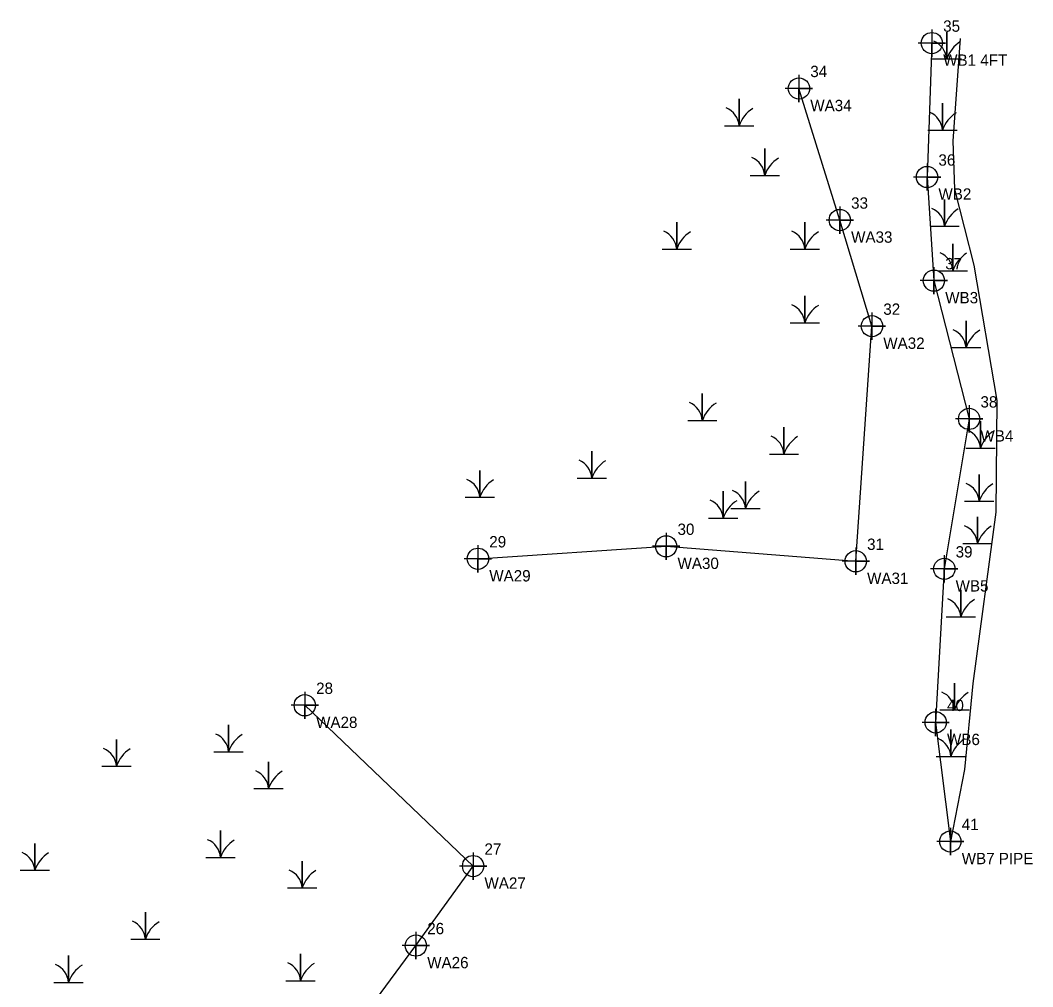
# Model space of a CAD drawing. Extents: x 2189822 to 2190837, y 387253 to 388663.
# Drawn here: x 2190230.2 to 2190453.2, y 388136.9 to 388349.8 of the extents above; entities that cross this region are included whole.
import ezdxf

# ---------------------------------------------------------------- set-up
doc = ezdxf.new("R2010")
doc.units = 0
for name, color, linetype in [('COGO Default Chain', 7, 'Continuous'), ('DTM Contours Major', 7, 'Continuous'), ('DTM Contours Minor', 7, 'Continuous'), ('Exist DTM Breakline Cogo Elevation', 7, 'Continuous'), ('Exist DTM Breakline Cogo Number', 7, 'Continuous')]:
    doc.layers.add(name, color=color, linetype=linetype)

msp = doc.modelspace()

# ---------------------------------------------------------------- linework, layer by layer
at = {"layer": 'DTM Contours Major'}
for points in [[(2190430.93, 388347.81), (2190430.93, 388341.81), (2190430.93, 388344.81), (2190433.93, 388344.81), (2190427.93, 388344.81)], [(2190401.66, 388337.81), (2190401.66, 388331.81), (2190401.66, 388334.81), (2190404.66, 388334.81), (2190398.66, 388334.81)], [(2190429.88, 388318.3), (2190429.88, 388312.3), (2190429.88, 388315.3), (2190432.88, 388315.3), (2190426.88, 388315.3)], [(2190410.65, 388308.82), (2190410.65, 388302.82), (2190410.65, 388305.82), (2190413.65, 388305.82), (2190407.65, 388305.82)], [(2190431.38, 388295.47), (2190431.38, 388289.47), (2190431.38, 388292.47), (2190434.38, 388292.47), (2190428.38, 388292.47)], [(2190417.74, 388285.44), (2190417.74, 388279.44), (2190417.74, 388282.44), (2190420.74, 388282.44), (2190414.74, 388282.44)], [(2190439.14, 388265.01), (2190439.14, 388259.01), (2190439.14, 388262.01), (2190442.14, 388262.01), (2190436.14, 388262.01)], [(2190372.42, 388236.94), (2190372.42, 388230.94), (2190372.42, 388233.94), (2190375.42, 388233.94), (2190369.42, 388233.94)], [(2190330.96, 388234.19), (2190330.96, 388228.19), (2190330.96, 388231.19), (2190333.96, 388231.19), (2190327.96, 388231.19)], [(2190414.17, 388233.64), (2190414.17, 388227.64), (2190414.17, 388230.64), (2190417.17, 388230.64), (2190411.17, 388230.64)], [(2190433.67, 388231.97), (2190433.67, 388225.97), (2190433.67, 388228.97), (2190436.67, 388228.97), (2190430.67, 388228.97)], [(2190292.82, 388201.91), (2190292.82, 388195.91), (2190292.82, 388198.91), (2190295.82, 388198.91), (2190289.82, 388198.91)], [(2190431.77, 388198.14), (2190431.77, 388192.14), (2190431.77, 388195.14), (2190434.77, 388195.14), (2190428.77, 388195.14)], [(2190435.01, 388171.9), (2190435.01, 388165.9), (2190435.01, 388168.9), (2190438.01, 388168.9), (2190432.01, 388168.9)], [(2190329.9, 388166.48), (2190329.9, 388160.48), (2190329.9, 388163.48), (2190332.9, 388163.48), (2190326.9, 388163.48)], [(2190317.29, 388148.97), (2190317.29, 388142.97), (2190317.29, 388145.97), (2190320.29, 388145.97), (2190314.29, 388145.97)]]:
    msp.add_lwpolyline(points, dxfattribs=at)
for centre in [(2190430.93, 388344.81), (2190401.66, 388334.81), (2190429.88, 388315.3), (2190410.65, 388305.82), (2190431.38, 388292.47), (2190417.74, 388282.44), (2190439.14, 388262.01), (2190372.42, 388233.94), (2190330.96, 388231.19), (2190414.17, 388230.64), (2190433.67, 388228.97), (2190292.82, 388198.91), (2190431.77, 388195.14), (2190435.01, 388168.9), (2190329.9, 388163.48), (2190317.29, 388145.97)]:
    msp.add_circle(centre, 2.34, dxfattribs=at)
at = {"layer": 'Exist DTM Breakline Cogo Elevation'}
for p, q in [((2190434.21, 388343.98), (2190434.21, 388343.98)), ((2190388.49, 388329.25), (2190388.49, 388329.25)), ((2190433.29, 388328.32), (2190433.29, 388328.32)), ((2190394.13, 388318.32), (2190394.13, 388318.32)), ((2190433.75, 388307.12), (2190433.75, 388307.12)), ((2190374.74, 388302.09), (2190374.74, 388302.09)), ((2190402.95, 388302.09), (2190402.95, 388302.09)), ((2190435.59, 388297.33), (2190435.59, 388297.33)), ((2190402.95, 388285.86), (2190402.95, 388285.86)), ((2190438.47, 388280.4), (2190438.47, 388280.4)), ((2190380.38, 388264.35), (2190380.38, 388264.35)), ((2190398.36, 388256.94), (2190398.36, 388256.94)), ((2190441.64, 388258.26), (2190441.64, 388258.26)), ((2190356.06, 388251.65), (2190356.06, 388251.65)), ((2190331.38, 388247.41), (2190331.38, 388247.41)), ((2190441.35, 388246.54), (2190441.35, 388246.54)), ((2190384.97, 388242.83), (2190384.97, 388242.83)), ((2190389.9, 388244.95), (2190389.9, 388244.95)), ((2190441, 388237.21), (2190441, 388237.21)), ((2190437.32, 388221.08), (2190437.32, 388221.08)), ((2190435.94, 388200.58), (2190435.94, 388200.58)), ((2190276.04, 388191.33), (2190276.04, 388191.33)), ((2190435.13, 388190.33), (2190435.13, 388190.33)), ((2190251.36, 388188.15), (2190251.36, 388188.15)), ((2190284.85, 388183.21), (2190284.85, 388183.21)), ((2190274.27, 388168.05), (2190274.27, 388168.05)), ((2190233.38, 388165.22), (2190233.38, 388165.22)), ((2190292.25, 388161.34), (2190292.25, 388161.34)), ((2190257.7, 388150.06), (2190257.7, 388150.06)), ((2190240.78, 388140.53), (2190240.78, 388140.53)), ((2190291.9, 388140.88), (2190291.9, 388140.88))]:
    msp.add_line(p, q, dxfattribs=at)
for points in [[(2190430.99, 388341.31), (2190434.21, 388341.31), (2190434.21, 388347.23), (2190434.21, 388341.31), (2190437.44, 388341.31)], [(2190385.27, 388326.58), (2190388.49, 388326.58), (2190388.49, 388332.5), (2190388.49, 388326.58), (2190391.72, 388326.58)], [(2190430.07, 388325.64), (2190433.29, 388325.64), (2190433.29, 388331.56), (2190433.29, 388325.64), (2190436.52, 388325.64)], [(2190390.91, 388315.64), (2190394.13, 388315.64), (2190394.13, 388321.56), (2190394.13, 388315.64), (2190397.36, 388315.64)], [(2190430.53, 388304.45), (2190433.75, 388304.45), (2190433.75, 388310.37), (2190433.75, 388304.45), (2190436.98, 388304.45)], [(2190371.52, 388299.42), (2190374.74, 388299.42), (2190374.74, 388305.33), (2190374.74, 388299.42), (2190377.97, 388299.42)], [(2190399.72, 388299.42), (2190402.95, 388299.42), (2190402.95, 388305.33), (2190402.95, 388299.42), (2190406.17, 388299.42)], [(2190432.37, 388294.66), (2190435.59, 388294.66), (2190435.59, 388300.58), (2190435.59, 388294.66), (2190438.82, 388294.66)], [(2190399.72, 388283.19), (2190402.95, 388283.19), (2190402.95, 388289.11), (2190402.95, 388283.19), (2190406.17, 388283.19)], [(2190435.25, 388277.73), (2190438.47, 388277.73), (2190438.47, 388283.64), (2190438.47, 388277.73), (2190441.7, 388277.73)], [(2190377.16, 388261.67), (2190380.38, 388261.67), (2190380.38, 388267.59), (2190380.38, 388261.67), (2190383.61, 388261.67)], [(2190438.42, 388255.59), (2190441.64, 388255.59), (2190441.64, 388261.5), (2190441.64, 388255.59), (2190444.87, 388255.59)], [(2190395.14, 388254.26), (2190398.36, 388254.26), (2190398.36, 388260.18), (2190398.36, 388254.26), (2190401.59, 388254.26)], [(2190352.83, 388248.97), (2190356.06, 388248.97), (2190356.06, 388254.89), (2190356.06, 388248.97), (2190359.29, 388248.97)], [(2190328.16, 388244.74), (2190331.38, 388244.74), (2190331.38, 388250.66), (2190331.38, 388244.74), (2190334.61, 388244.74)], [(2190438.12, 388243.86), (2190441.35, 388243.86), (2190441.35, 388249.78), (2190441.35, 388243.86), (2190444.58, 388243.86)], [(2190386.68, 388242.27), (2190389.9, 388242.27), (2190389.9, 388248.19), (2190389.9, 388242.27), (2190393.13, 388242.27)], [(2190381.74, 388240.15), (2190384.97, 388240.15), (2190384.97, 388246.07), (2190384.97, 388240.15), (2190388.19, 388240.15)], [(2190437.78, 388234.53), (2190441, 388234.53), (2190441, 388240.45), (2190441, 388234.53), (2190444.23, 388234.53)], [(2190434.1, 388218.41), (2190437.32, 388218.41), (2190437.32, 388224.32), (2190437.32, 388218.41), (2190440.55, 388218.41)], [(2190432.71, 388197.9), (2190435.94, 388197.9), (2190435.94, 388203.82), (2190435.94, 388197.9), (2190439.16, 388197.9)], [(2190272.81, 388188.65), (2190276.04, 388188.65), (2190276.04, 388194.57), (2190276.04, 388188.65), (2190279.26, 388188.65)], [(2190431.91, 388187.65), (2190435.13, 388187.65), (2190435.13, 388193.57), (2190435.13, 388187.65), (2190438.36, 388187.65)], [(2190248.13, 388185.48), (2190251.36, 388185.48), (2190251.36, 388191.4), (2190251.36, 388185.48), (2190254.59, 388185.48)], [(2190281.62, 388180.54), (2190284.85, 388180.54), (2190284.85, 388186.46), (2190284.85, 388180.54), (2190288.08, 388180.54)], [(2190271.05, 388165.37), (2190274.27, 388165.37), (2190274.27, 388171.29), (2190274.27, 388165.37), (2190277.5, 388165.37)], [(2190230.16, 388162.55), (2190233.38, 388162.55), (2190233.38, 388168.47), (2190233.38, 388162.55), (2190236.61, 388162.55)], [(2190289.03, 388158.67), (2190292.25, 388158.67), (2190292.25, 388164.59), (2190292.25, 388158.67), (2190295.48, 388158.67)], [(2190254.48, 388147.38), (2190257.71, 388147.38), (2190257.71, 388153.3), (2190257.71, 388147.38), (2190260.93, 388147.38)], [(2190237.56, 388137.86), (2190240.78, 388137.86), (2190240.78, 388143.77), (2190240.78, 388137.86), (2190244.01, 388137.86)], [(2190288.67, 388138.21), (2190291.9, 388138.21), (2190291.9, 388144.13), (2190291.9, 388138.21), (2190295.13, 388138.21)]]:
    msp.add_lwpolyline(points, dxfattribs=at)
for centre, radius, start, end in [((2190429.61, 388340.97), 4.61, 4.1403, 67.535), ((2190441.05, 388339.03), 7.21, 122.1274, 161.6222), ((2190383.89, 388326.25), 4.61, 4.1403, 67.535), ((2190395.33, 388324.31), 7.21, 122.1274, 161.6222), ((2190428.69, 388325.31), 4.61, 4.1403, 67.535), ((2190440.13, 388323.37), 7.21, 122.1274, 161.6222), ((2190389.53, 388315.31), 4.61, 4.1403, 67.535), ((2190400.97, 388313.37), 7.21, 122.1274, 161.6222), ((2190429.15, 388304.12), 4.61, 4.1403, 67.535), ((2190440.59, 388302.18), 7.21, 122.1274, 161.6222), ((2190370.14, 388299.08), 4.61, 4.1403, 67.535), ((2190381.58, 388297.14), 7.21, 122.1274, 161.6222), ((2190398.35, 388299.08), 4.61, 4.1403, 67.535), ((2190409.79, 388297.14), 7.21, 122.1274, 161.6222), ((2190430.99, 388294.33), 4.61, 4.1403, 67.535), ((2190442.43, 388292.39), 7.21, 122.1274, 161.6222), ((2190398.35, 388282.86), 4.61, 4.1403, 67.535), ((2190409.79, 388280.92), 7.21, 122.1274, 161.6222), ((2190433.87, 388277.39), 4.61, 4.1403, 67.535), ((2190445.31, 388275.45), 7.21, 122.1274, 161.6222), ((2190375.78, 388261.34), 4.61, 4.1403, 67.535), ((2190387.23, 388259.4), 7.21, 122.1274, 161.6222), ((2190437.04, 388255.25), 4.61, 4.1403, 67.535), ((2190448.48, 388253.31), 7.21, 122.1274, 161.6222), ((2190393.76, 388253.93), 4.61, 4.1403, 67.535), ((2190405.2, 388251.99), 7.21, 122.1274, 161.6222), ((2190351.46, 388248.64), 4.61, 4.1403, 67.535), ((2190362.9, 388246.7), 7.21, 122.1274, 161.6222), ((2190326.78, 388244.41), 4.61, 4.1403, 67.535), ((2190338.22, 388242.47), 7.21, 122.1274, 161.6222), ((2190436.75, 388243.53), 4.61, 4.1403, 67.535), ((2190448.19, 388241.59), 7.21, 122.1274, 161.6222), ((2190385.3, 388241.94), 4.61, 4.1403, 67.535), ((2190396.74, 388240), 7.21, 122.1274, 161.6222), ((2190380.37, 388239.82), 4.61, 4.1403, 67.535), ((2190391.81, 388237.88), 7.21, 122.1274, 161.6222), ((2190436.4, 388234.2), 4.61, 4.1403, 67.535), ((2190447.85, 388232.26), 7.21, 122.1274, 161.6222), ((2190432.72, 388218.07), 4.61, 4.1403, 67.535), ((2190444.16, 388216.13), 7.21, 122.1274, 161.6222), ((2190431.34, 388197.57), 4.61, 4.1403, 67.535), ((2190442.78, 388195.63), 7.21, 122.1274, 161.6222), ((2190271.44, 388188.32), 4.61, 4.1403, 67.535), ((2190282.88, 388186.38), 7.21, 122.1274, 161.6222), ((2190430.53, 388187.32), 4.61, 4.1403, 67.535), ((2190441.97, 388185.38), 7.21, 122.1274, 161.6222), ((2190246.76, 388185.14), 4.61, 4.1403, 67.535), ((2190258.2, 388183.21), 7.21, 122.1274, 161.6222), ((2190280.25, 388180.21), 4.61, 4.1403, 67.535), ((2190291.69, 388178.27), 7.21, 122.1274, 161.6222), ((2190269.67, 388165.04), 4.61, 4.1403, 67.535), ((2190281.12, 388163.1), 7.21, 122.1274, 161.6222), ((2190228.78, 388162.22), 4.61, 4.1403, 67.535), ((2190240.22, 388160.28), 7.21, 122.1274, 161.6222), ((2190287.65, 388158.34), 4.61, 4.1403, 67.535), ((2190299.09, 388156.4), 7.21, 122.1274, 161.6222), ((2190253.11, 388147.05), 4.61, 4.1403, 67.535), ((2190264.55, 388145.11), 7.21, 122.1274, 161.6222), ((2190236.18, 388137.52), 4.61, 4.1403, 67.535), ((2190247.63, 388135.58), 7.21, 122.1274, 161.6222), ((2190287.3, 388137.88), 4.61, 4.1403, 67.535), ((2190298.74, 388135.94), 7.21, 122.1274, 161.6222)]:
    msp.add_arc(centre, radius, start, end, dxfattribs=at)
at = {"layer": 'Exist DTM Breakline Cogo Number'}
for points in [[(2190437.15, 388345.85), (2190435.54, 388323.27), (2190435.94, 388312.59), (2190440.18, 388295.86), (2190445.21, 388266.03), (2190445.01, 388241.43), (2190439.97, 388203.74), (2190438.16, 388184.79), (2190435.01, 388168.9)], [(2190430.93, 388344.81), (2190429.88, 388315.3), (2190431.38, 388292.47), (2190439.14, 388262.01), (2190433.67, 388228.97), (2190431.77, 388195.14), (2190435.01, 388168.9)], [(2190330.96, 388231.19), (2190372.42, 388233.94), (2190414.17, 388230.64), (2190417.74, 388282.44), (2190410.65, 388305.82), (2190401.66, 388334.81)], [(2190303.02, 388126.66), (2190317.29, 388145.97), (2190329.9, 388163.48), (2190292.82, 388198.91)]]:
    msp.add_lwpolyline(points, dxfattribs=at)

# ---------------------------------------------------------------- texts
at = {"layer": 'COGO Default Chain'}
for s, p in [('WB1 4FT', (2190433.43, 388339.81)), ('WA34', (2190404.16, 388329.81)), ('WB2', (2190432.38, 388310.3)), ('WA33', (2190413.15, 388300.82)), ('WB3', (2190433.88, 388287.47)), ('WA32', (2190420.24, 388277.44)), ('WB4', (2190441.64, 388257.01)), ('WA30', (2190374.92, 388228.94)), ('WA29', (2190333.46, 388226.19)), ('WA31', (2190416.67, 388225.64)), ('WB5', (2190436.17, 388223.97)), ('WA28', (2190295.32, 388193.91)), ('WB6', (2190434.27, 388190.14)), ('WB7 PIPE', (2190437.51, 388163.9)), ('WA27', (2190332.4, 388158.48)), ('WA26', (2190319.79, 388140.97))]:
    msp.add_text(s, height=2.5, dxfattribs=at).set_placement(p)
at = {"layer": 'DTM Contours Minor'}
for s, p in [('35', (2190433.43, 388347.31)), ('34', (2190404.16, 388337.31)), ('36', (2190432.38, 388317.8)), ('33', (2190413.15, 388308.32)), ('37', (2190433.88, 388294.97)), ('32', (2190420.24, 388284.94)), ('38', (2190441.64, 388264.51)), ('30', (2190374.92, 388236.44)), ('29', (2190333.46, 388233.69)), ('31', (2190416.67, 388233.14)), ('39', (2190436.17, 388231.47)), ('28', (2190295.32, 388201.41)), ('40', (2190434.27, 388197.64)), ('41', (2190437.51, 388171.4)), ('27', (2190332.4, 388165.98)), ('26', (2190319.79, 388148.47))]:
    msp.add_text(s, height=2.5, dxfattribs=at).set_placement(p)

doc.saveas('drawing.dxf')
